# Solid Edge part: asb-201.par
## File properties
Last saved by: nakano
Revision: 75
Density: 2446.69313201344 kg/m^3
Accuracy: 0.990
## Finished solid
Body 1: solid body, 61 faces, 156 edges, 76 vertices.
  Faces by surface: cylinder 37, plane 24
  Edges by curve: line 82, circle 74
Bounding box of the edges (mm): 75.692 x 33.477 x 42.850, from (0, 0, -42.8498) to (75.692, 33.4772, 0).
Cylindrical faces by radius (mm): R0.254 x3, R1.1938 x10, R1.5875 x5, R2.1844 x6, R2.54 x10, R4.0005 x3
Planar faces by outward normal: +x 4, +y 4, +z 5, -x 4, -y 1, -z 6
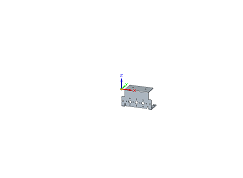
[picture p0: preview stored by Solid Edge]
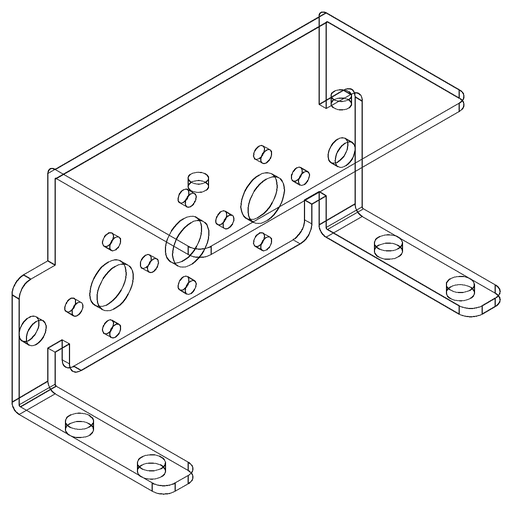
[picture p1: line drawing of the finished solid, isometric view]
